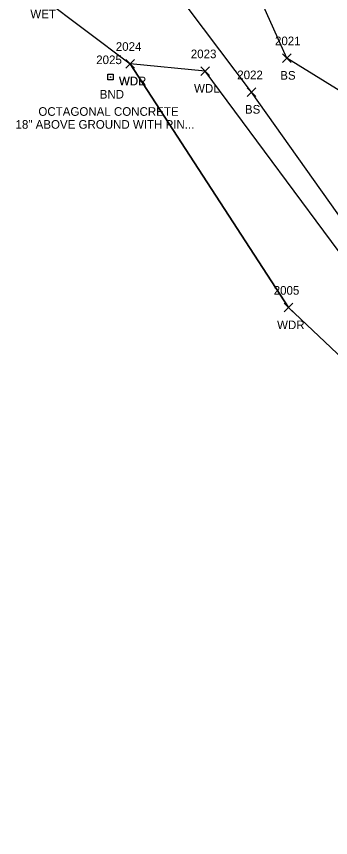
# Model space of a CAD drawing. Extents: x 1623612 to 1625808, y 621345 to 627748.
# Drawn here: x 1624179.2 to 1624252.1, y 626606.1 to 626796.7 of the extents above; entities that cross this region are included whole.
import ezdxf

# ---------------------------------------------------------------- set-up
doc = ezdxf.new("R2010")
doc.units = 0
for name, color, linetype in [('L_A', 7, 'Continuous'), ('L_I', 7, 'Continuous'), ('L_TIC', 7, 'Continuous'), ('LAWA', 7, 'Continuous'), ('LELB', 7, 'Continuous'), ('Level 18', 7, 'Continuous'), ('LSOGP', 7, 'Continuous'), ('M_A', 7, 'Continuous'), ('M_C', 7, 'Continuous'), ('M_I', 7, 'Continuous')]:
    doc.layers.add(name, color=color, linetype=linetype)

msp = doc.modelspace()

# ---------------------------------------------------------------- linework, layer by layer
at = {"layer": 'L_TIC'}
for points in [[(1624241, 626786.06), (1624243, 626788.06)], [(1624243, 626786.06), (1624241, 626788.06)], [(1624204.61, 626784.75), (1624206.61, 626786.75)], [(1624206.61, 626784.75), (1624204.61, 626786.75)], [(1624204.61, 626784.75), (1624206.61, 626786.75)], [(1624206.61, 626784.75), (1624204.61, 626786.75)], [(1624222.02, 626783.04), (1624224.02, 626785.04)], [(1624224.02, 626783.04), (1624222.02, 626785.04)], [(1624232.8, 626778.17), (1624234.8, 626780.17)], [(1624234.8, 626778.17), (1624232.8, 626780.17)], [(1624241.34, 626728.15), (1624243.34, 626730.15)], [(1624243.34, 626728.15), (1624241.34, 626730.15)]]:
    msp.add_lwpolyline(points, dxfattribs=at)
at = {"layer": 'LAWA'}
for points in [[(1624323.19, 626627.03), (1624330.05, 626634.11), (1624301.06, 626669.94), (1624284.79, 626705.91), (1624257.42, 626737.63), (1624223.02, 626784.04), (1624205.61, 626785.75)], [(1624323.19, 626627.03), (1624293.2, 626666.35), (1624273.4, 626699.89), (1624242.34, 626729.15), (1624205.61, 626785.75)]]:
    msp.add_lwpolyline(points, dxfattribs=at)
at = {"layer": 'LELB'}
for points in [[(1624380.03, 626635.67), (1624388.85, 626639.75), (1624394.9, 626646.05), (1624375.51, 626671.51), (1624340.23, 626704.74), (1624305.85, 626733.46), (1624282.24, 626762.21), (1624242, 626787.06), (1624227.53, 626819.4), (1624211.45, 626808.79)], [(1624388.85, 626639.75), (1624369.38, 626664.3), (1624336.32, 626701.97), (1624299.54, 626729.32), (1624260.87, 626741.01), (1624233.8, 626779.17), (1624211.45, 626808.79)]]:
    msp.add_lwpolyline(points, dxfattribs=at)
at = {"layer": 'Level 18'}
msp.add_lwpolyline([(1624200.43, 626783.3), (1624201.68, 626783.3), (1624201.68, 626782.05), (1624200.43, 626782.05)], close=True, dxfattribs=at)
msp.add_circle((1624201.06, 626782.67), 0.0833, dxfattribs=at)
at = {"layer": 'LSOGP'}
msp.add_lwpolyline([(1624185.05, 626801.31), (1624205.61, 626785.75), (1624242.34, 626729.15), (1624273.4, 626699.89), (1624293.2, 626666.35), (1624323.19, 626627.03), (1624337.94, 626595.4), (1624375.16, 626557.28)], dxfattribs=at)

# ---------------------------------------------------------------- texts
at = {"layer": 'L_A'}
for s, p in [('WET', (1624182.43, 626796.31)), ('WDR', (1624202.98, 626780.75)), ('WDL', (1624203.03, 626780.75)), ('BS', (1624240.44, 626782.06)), ('WDL', (1624220.43, 626779.04)), ('BS', (1624232.24, 626774.17)), ('WDR', (1624239.71, 626724.15))]:
    msp.add_text(s, height=2, dxfattribs=at).set_placement(p)
at = {"layer": 'L_I'}
for s, p in [('2021', (1624239.22, 626790.06)), ('2024', (1624202.27, 626788.75)), ('2024', (1624202.27, 626788.75)), ('2023', (1624219.68, 626787.04)), ('2022', (1624230.46, 626782.17)), ('2005', (1624238.93, 626732.15))]:
    msp.add_text(s, height=2, dxfattribs=at).set_placement(p)
at = {"layer": 'M_A'}
msp.add_text('BND', height=2, dxfattribs=at).set_placement((1624198.54, 626777.67))
at = {"layer": 'M_C'}
for s, p in [('OCTAGONAL CONCRETE', (1624184.3, 626773.67)), ('18" ABOVE GROUND WITH PIN...', (1624178.99, 626770.67))]:
    msp.add_text(s, height=2, dxfattribs=at).set_placement(p)
at = {"layer": 'M_I'}
msp.add_text('2025', height=2, dxfattribs=at).set_placement((1624197.72, 626785.67))

doc.saveas('drawing.dxf')
